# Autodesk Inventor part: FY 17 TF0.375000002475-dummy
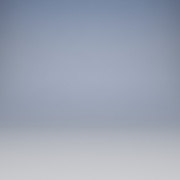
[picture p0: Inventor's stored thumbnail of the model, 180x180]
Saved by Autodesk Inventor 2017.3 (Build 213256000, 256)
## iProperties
Part Number: FY 17 TF0.375000002475-dummy
Material: Generic
Catalog Web Link: www.cadenas.de
Description: AYF_001HC_HH_HY-dummy-Y-bearing square flanged units
Vendor: SKF
Document SubType Name: Modeling
Designer: partserver
Manufacturer: SKF
Density: 1 g/cm^3
Appearance: PSOLRGB-175-175-175
Category: PARTsolutions
Company: SKF
Title: FY 17 TF0.375000002475-dummy
Author: Cadenas PARTsolutions
Comments: Y-bearing square flanged units
PSOL_IDENT_0: {$CADENAS_DATA\23d-libs\skf\bearings_units_and_housings\bearing_units\ball_bearing_units\y-units\y-b
PSOL_IDENT_1: earing_square_flanged_units_parts\ayf_001hc_hh_hy_dummy.prj},219 {VTYP=3D},{NB=FY 17 TF0.37500000247
PSOL_IDENT_2: 5-dummy},{LINA=FY 17 TF0.375000002475-dummy},{NN=AYF_001HC_HH_HY-dummy},{DATE=20.08.2020 13:45:20},{
PSOL_IDENT_3: GEOMDATE=30.07.2020 09:59:06},{VERSION=},{LINEID=51990},{WBVAR=COVER},{WBNUMERIC=}  {NB=FY 17 TF0.37
PSOL_IDENT_4: 5000002475-dummy},{LINA=FY 17 TF0.375000002475-dummy},{KT=DUMMY},{DESIGNATION=FY 17 TF},{HOUSING=FY
PSOL_IDENT_5: 503 M},{BEARING=YAR 203-2F},{COVER=},{DD=17},{DDX=},{DDALG=17.000},{DD1=24.200},{DD2=MIN},{DD3=},{AA
PSOL_IDENT_6: LG=26.000},{A=26},{AX=},{AXX=},{A1ALG=11.000},{A1=11},{A1X=},{A1XX=},{A3ALG=3.200},{A3=3.2},{A3X=},{
PSOL_IDENT_7: A5ALG=0.000},{A5=},{A5X=},{A5XX=},{B=27.400},{B1=MIN},{B1X=},{B4ALG=4.000},{B4=4},{B4X=},{DAAALG=55.
PSOL_IDENT_8: 600},{DAA=55.6},{DAAX=},{DB=MIN},{DB1=50.000},{DB1X=},{DB2=53.000},{DB2X=},{HA=},{J=54.000},{JX=},{J
PSOL_IDENT_9: XX=},{L=76.000},{LX=},{LXX=},{N=11.500},{NX=},{NXX=},{SS1=15.900},{SS1X=},{T=32.900},{TX=},{DN=6.500
PSOL_IDENT_10: },{SWN=7},{GN=1/4-28 SAE-LT},{RG=1/4-28 UNF},{RGX=},{R1=19},{R1X=},{J6=66},{J7=14.500},{N4=4},{D=40.
PSOL_IDENT_11: 000},{C=12.000},{R12=0.300},{DW=6.747},{B3=MIN},{PITCH=28.500},{LOAD1=9.560},{LOAD2=4.750},{LOAD3=0.
PSOL_IDENT_12: 200},{SPEED1=9500},{II=1},{Z=8},{MASS=0.370},{MASSX=},{G2=M6x0.75},{HKSGS=3},{RTTGS=4},{ALPHA=},{GAL
PSOL_IDENT_13: G=10.000},{G=10},{GX=},{GXX=},{GINALG=0.375},{GIN=0.375000002475},{GINX=},{GINXX=},{EC=},{BS=},{SLEE
PSOL_IDENT_14: VE=},{POPULAR=},{D1=MIN},{K=1.3},{CC1=3.6},{BRGTYP=BBY_006},{COVERALG=  '', 'No end cover' },{SUPPRE
PSOL_IDENT_15: SSED=unsuppressed},{TC=FY 17 TF}
NB: FY 17 TF0.375000002475-dummy
NN: AYF_001HC_HH_HY-dummy
NT: Y-bearing square flanged units
NBSYN: $TC.$GIN.-dummy
LINA: FY 17 TF0.375000002475-dummy
CATALOG: SKF
DESIGNATION: FY 17 TF
HOUSING: FY 503 M
BEARING: YAR 203-2F
COVER: No end cover
DD: 17
DD1: 24.2
DD2: 0
A: 26
A1: 11
A3: 3.2
B: 27.4
B1: 0
B4: 4
DAA: 55.6
DB: 0
DB1: 50
DB2: 53
J: 54
L: 76
N: 11.5
SS1: 15.9
T: 32.9
DN: 6.5
SWN: 7
GN: 1/4-28 SAE-LT
RG: 1/4-28 UNF
R1: 19
J6: 66
J7: 14.5
N4: 4
D: 40
C: 12
R12: 0.3
DW: 6.747
B3: 0
PITCH: 28.5
LOAD1: 9.56
LOAD2: 4.75
LOAD3: 0.2
SPEED1: 9500
II: 1
Z: 8
MASS: 0.37
G2: M6x0.75
HKSGS: 3
RTTGS: 4
G: 10
GIN: 0.375000002475
D1: 0
K: 1.3
CC1: 3.6
BRGTYP: BBY_006
COVERALG: '', 'No end cover'
SUPPLIER: SKF
ARTICLENO: FY 17 TF0.375000002475-dummy
BOMINFO: FY 17 TF0.375000002475-dummy
CREATOR: CADENAS GmbH
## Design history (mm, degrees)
node "brg_XY"
node "brg_YZ"
node "brg_ZX"
node "brg_X"
node "brg_Y"
node "brg_Z"
node "brg_Center"
node "brg1_XY"
node "brg1_YZ"
node "brg1_ZX"
node "brg1_X"
node "brg1_Y"
node "brg1_Z"
node "brg1_Center"
node "dummy_XY"
node "dummy_YZ"
node "dummy_ZX"
node "dummy_X"
node "dummy_Y"
node "dummy_Z"
node "dummy_Center"
